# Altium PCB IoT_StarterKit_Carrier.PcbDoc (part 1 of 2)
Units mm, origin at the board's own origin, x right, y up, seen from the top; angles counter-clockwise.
Board outline 84.71 x 84.24 mm, 4 copper layers (Top, PWR, MID, Bottom), stack 1.612 mm thick; 101 components, 113 nets, 468 pads, 142 vias.
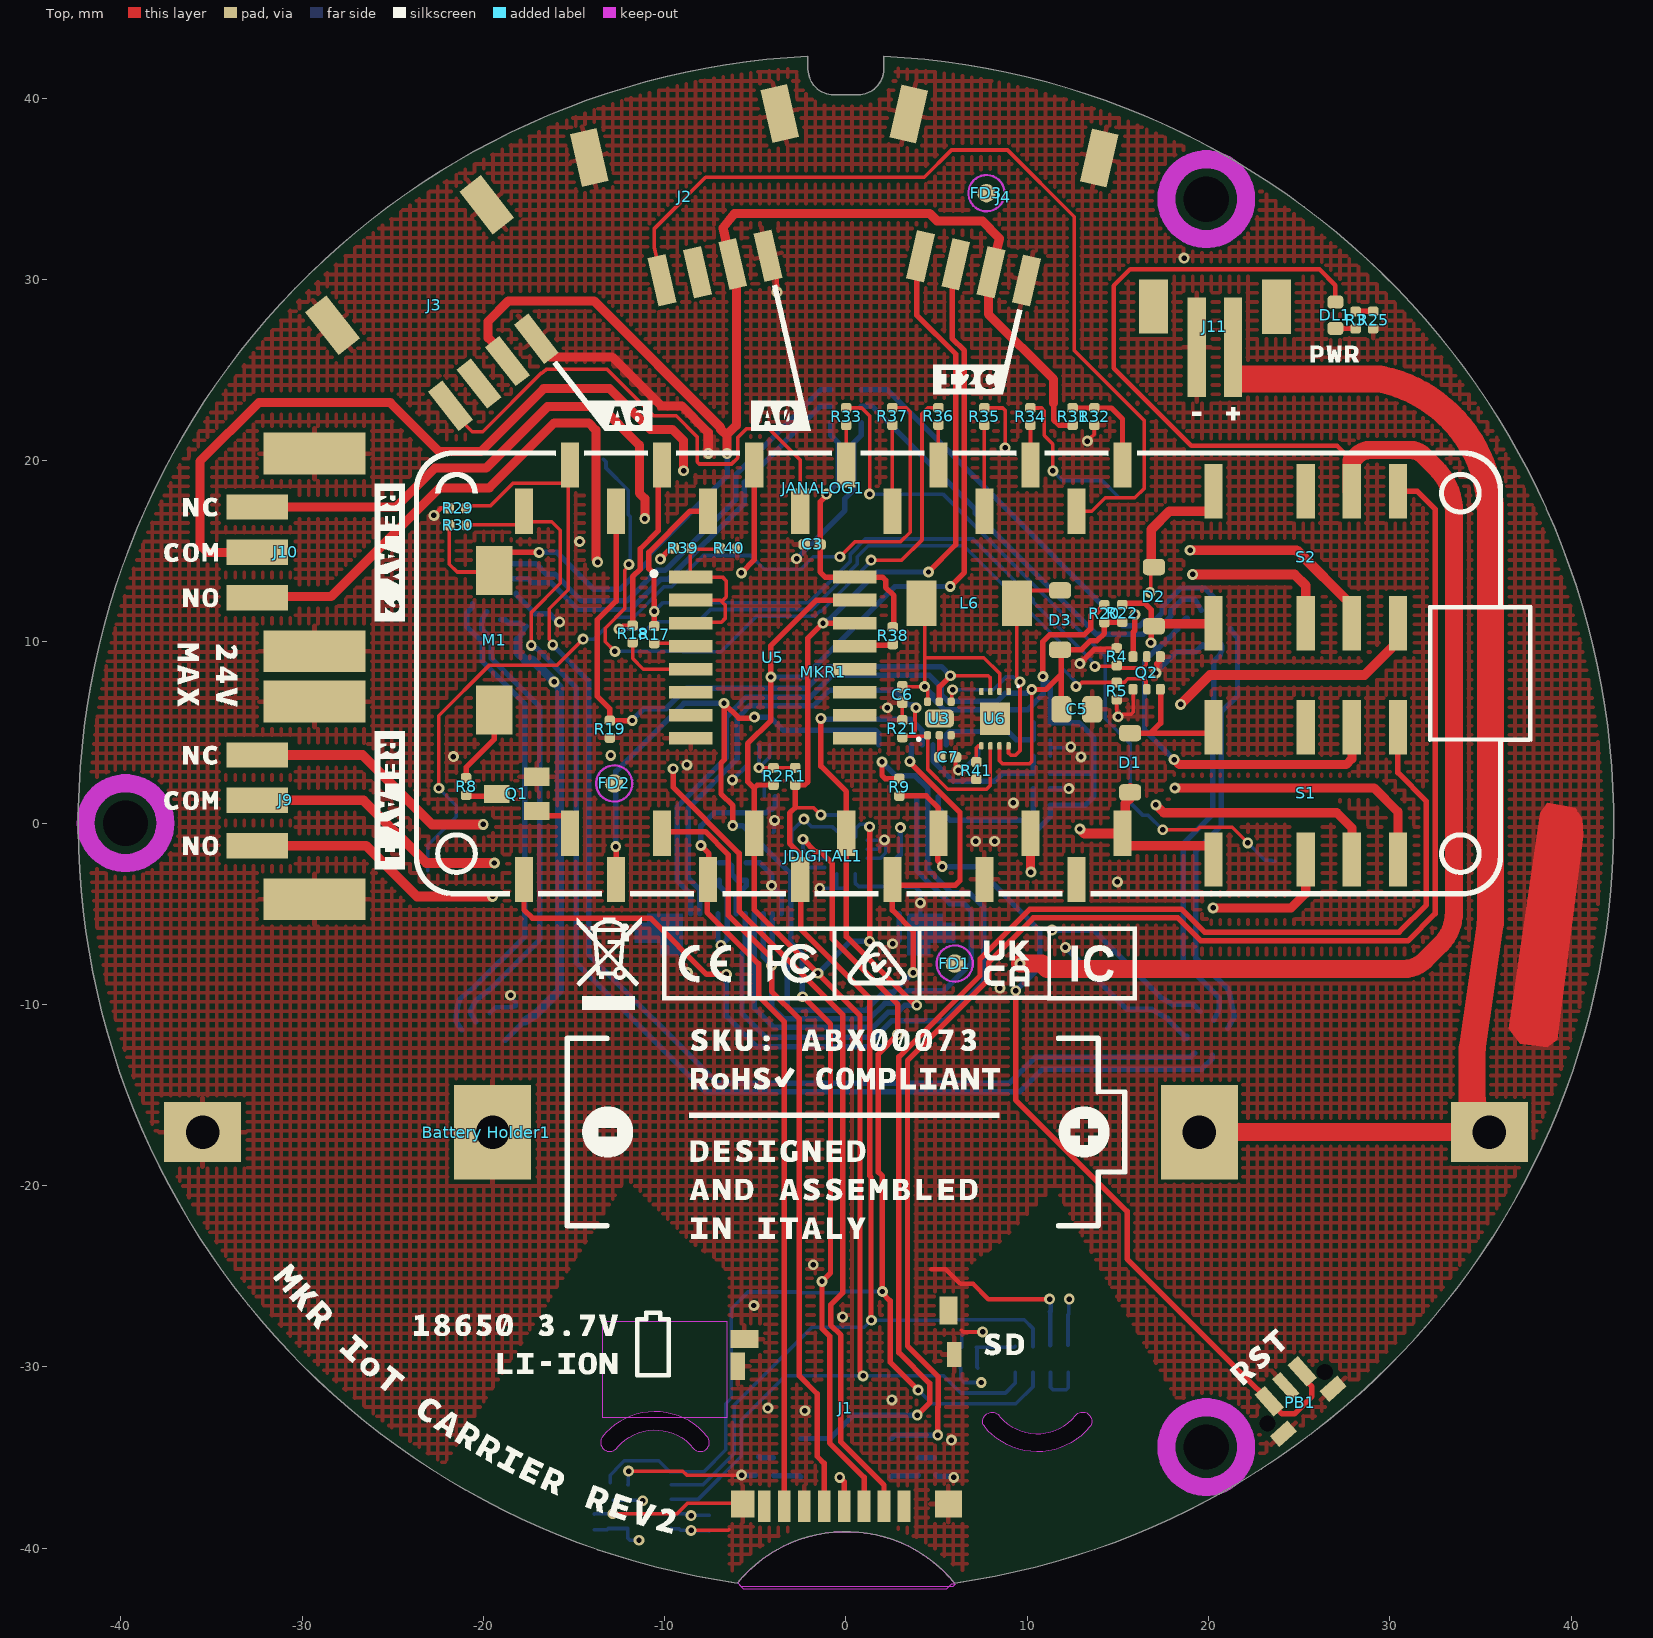
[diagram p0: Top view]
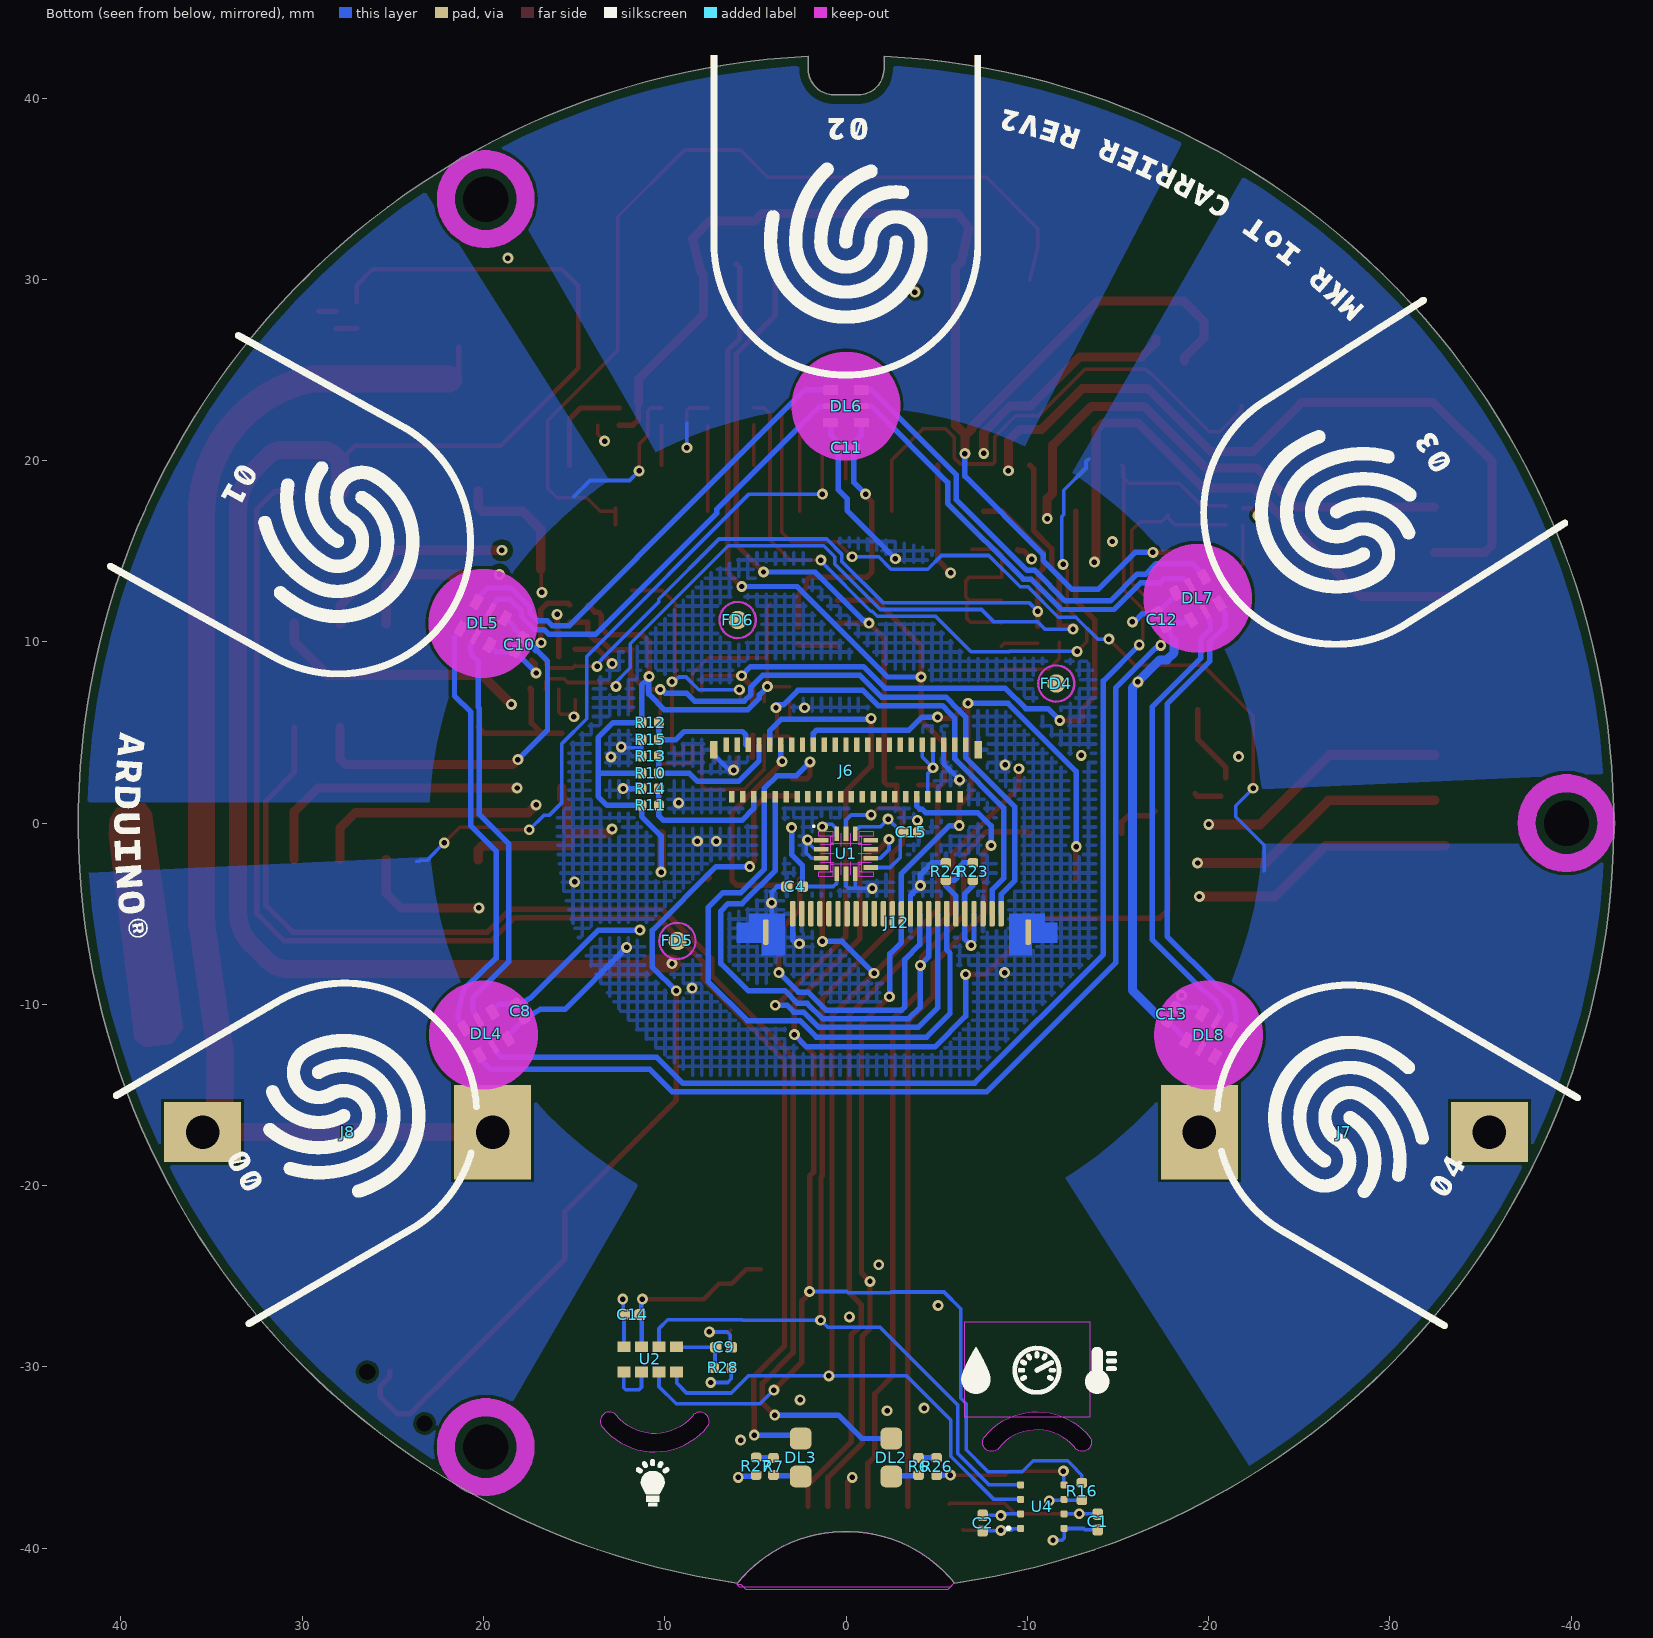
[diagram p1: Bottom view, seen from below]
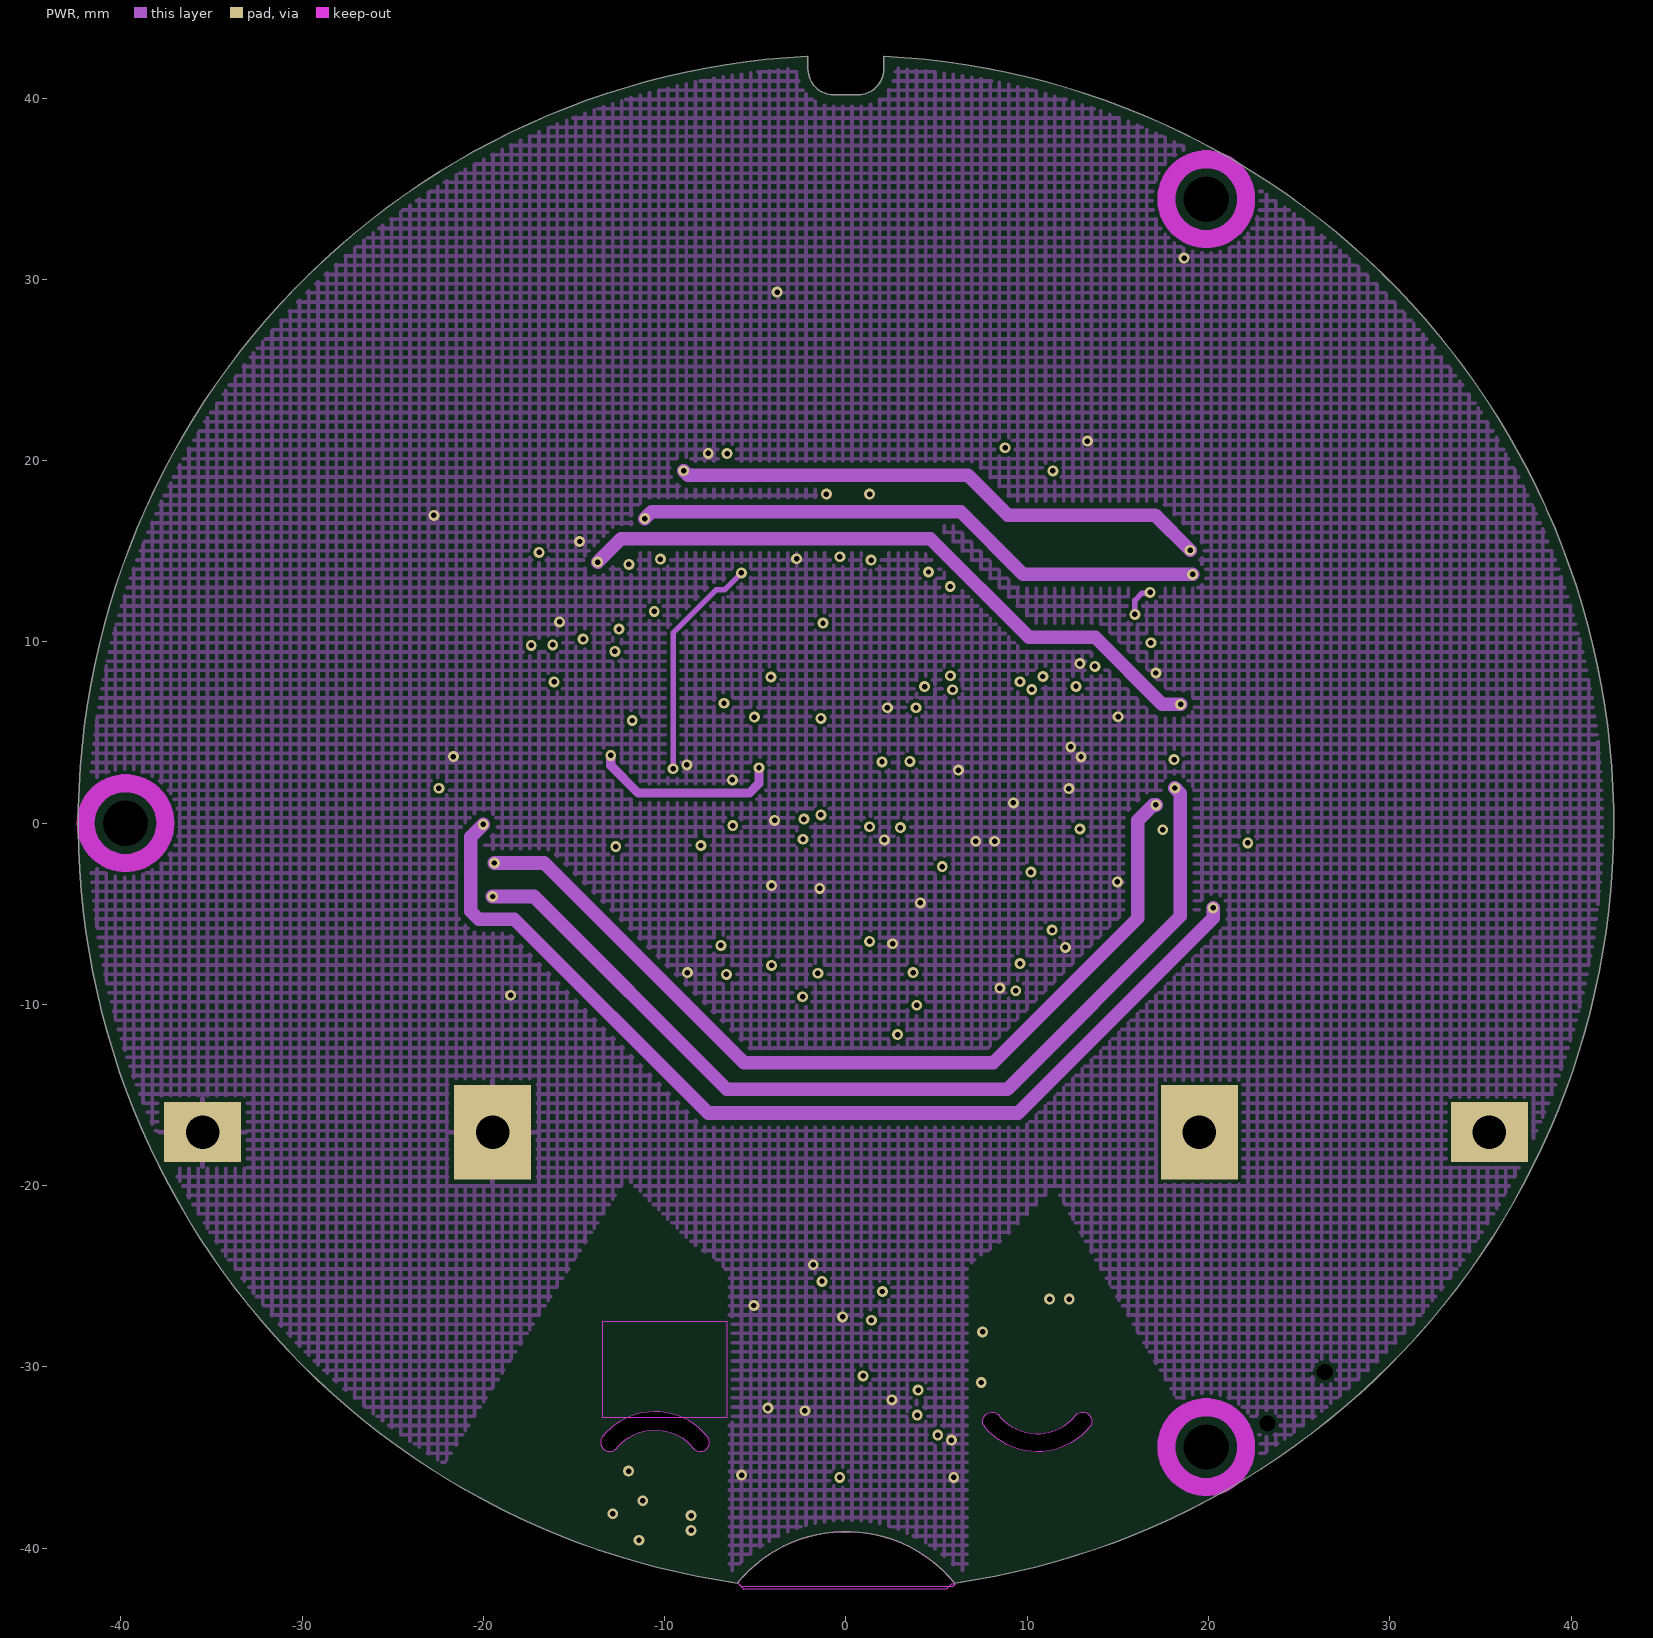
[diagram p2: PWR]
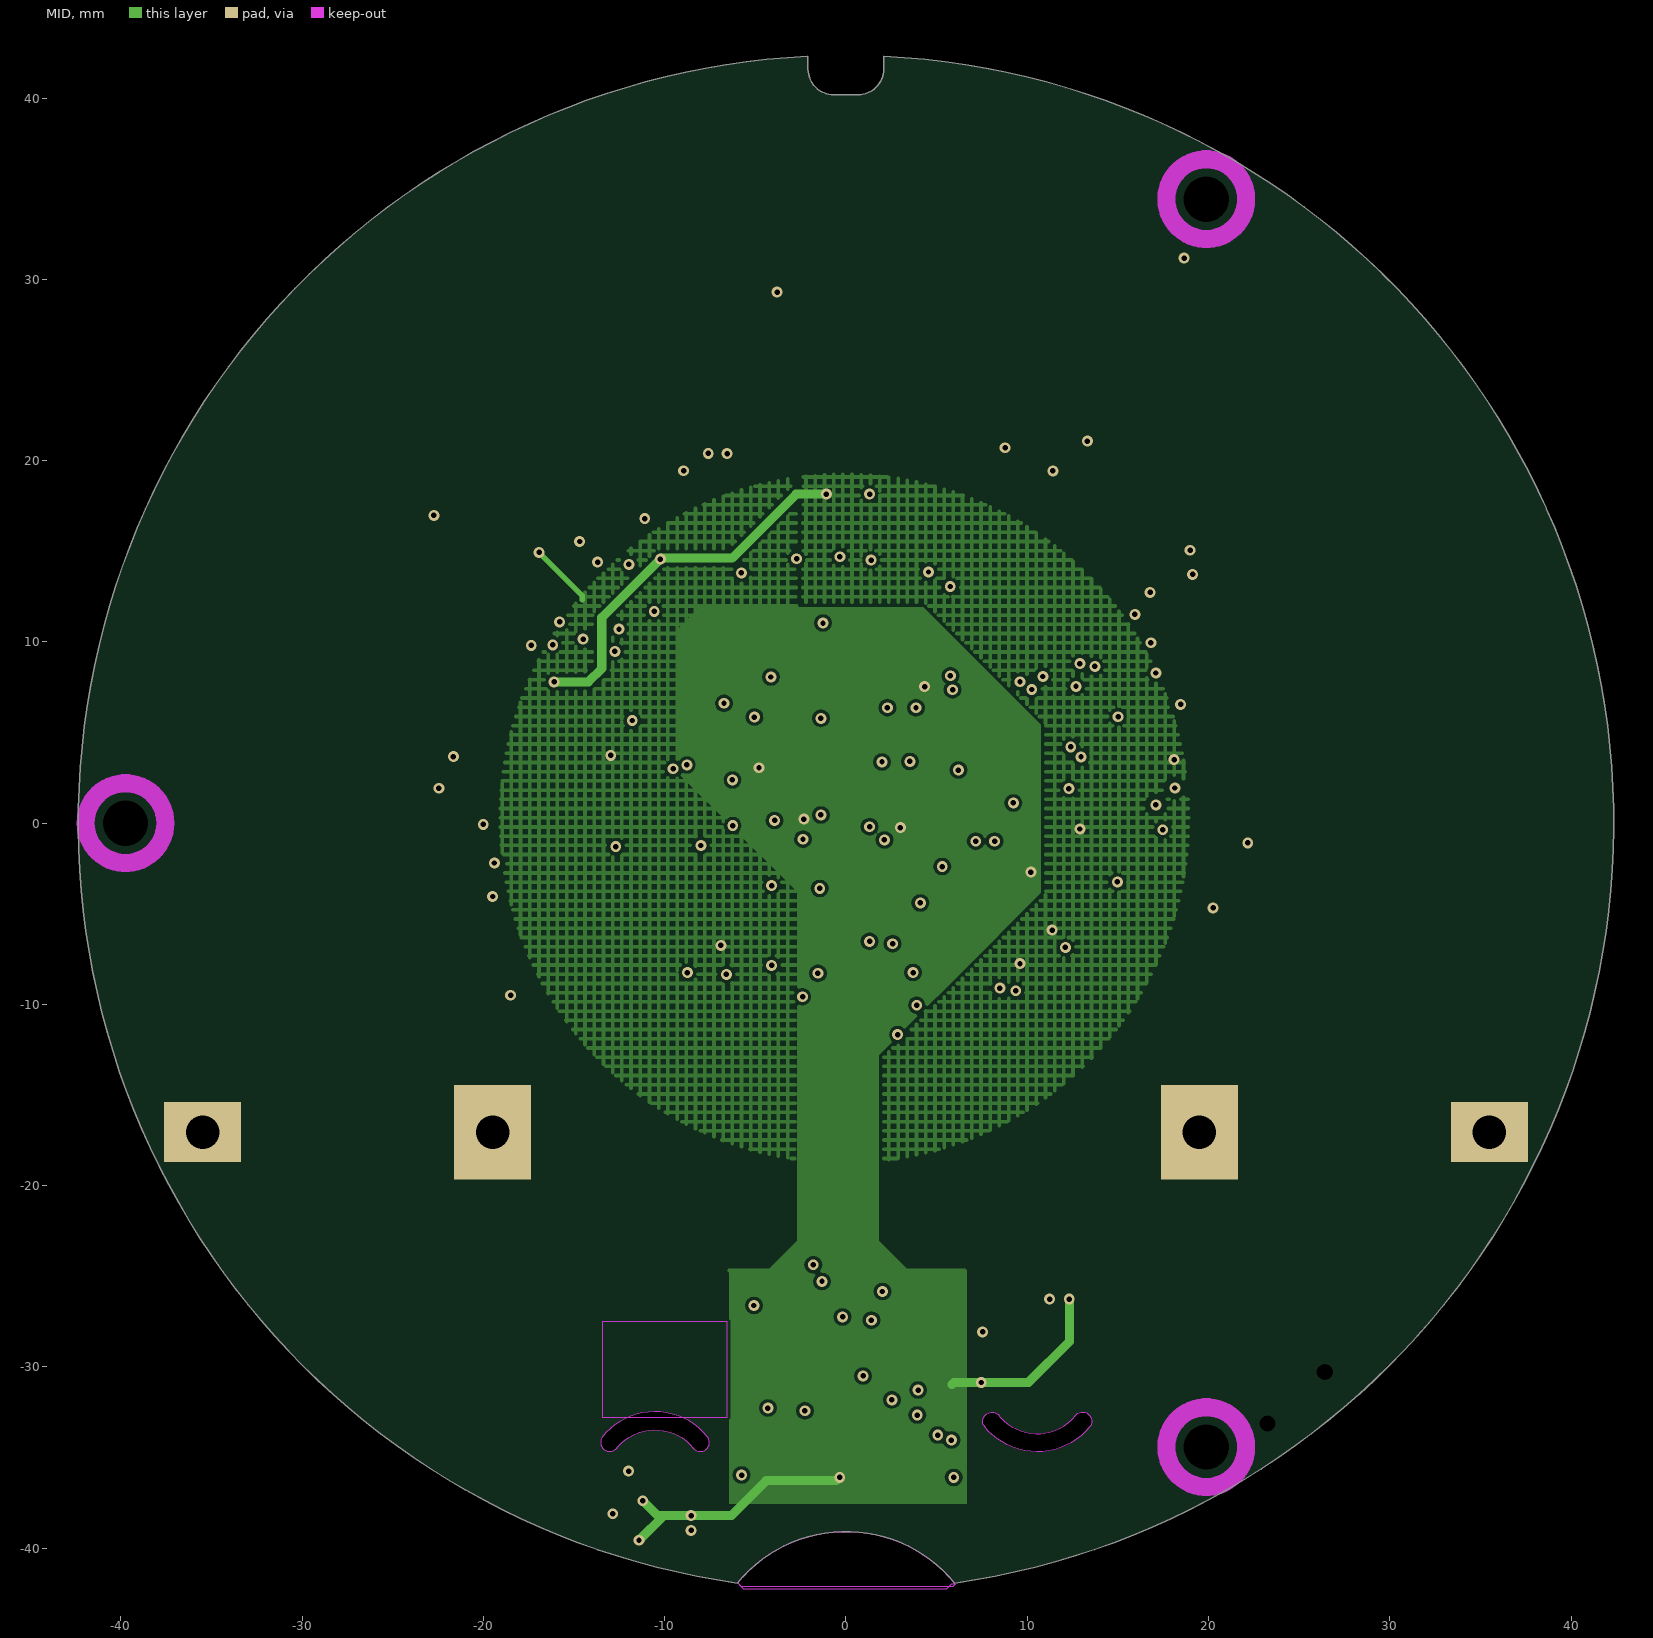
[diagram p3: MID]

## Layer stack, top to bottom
Top Solder: solder mask 0.01, Solder Resist, Dk 3.5
Top: signal copper 0.035
Dielectric 1: prepreg 0.356, FR-4, Dk 4.1
PWR: signal copper 0.035
Dielectric3: core 0.76, FR-4, Dk 4.8
MID: signal copper 0.035
Dielectric2: prepreg 0.356, FR-4, Dk 4.1
Bottom: signal copper 0.035
Bottom Solder: solder mask 0.0102, Solder Resist, Dk 3.5

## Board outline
-1.339,40.336 -1.079,40.228 -0.813,40.175 -0.672,40.168 0.656,40.168 0.797,40.175 1.063,40.228 1.323,40.336 1.558,40.493 1.757,40.692 1.914,40.927 2.022,41.187 2.074,41.453 2.081,41.594 2.081,42.306 2.082,42.306 cw(c0,0) 5.992,-41.931 ccw(c0,-46.8) -5.992,-41.931 cw(c0,0) -2.099,42.305 -2.098,42.285 -2.098,41.594 -2.091,41.453 -2.038,41.187 -1.93,40.927 -1.773,40.692 -1.574,40.493
cut-out: 7.614,-33.261 cw(c8.054,-33.008) 8.494,-32.755 ccw(c10.549,-30.949) 12.667,-32.68 cw(c13.055,-32.997) 13.555,-33.012 cw(c13.055,-32.997) 13.442,-33.314 cw(c10.549,-30.949)
cut-out: -13.475,-33.9 ccw(c-13.035,-34.153) -12.596,-34.406 cw(c-10.54,-36.212) -8.422,-34.481 ccw(c-8.035,-34.164) -7.534,-34.149 ccw(c-8.034,-34.164) -7.647,-33.847 ccw(c-10.54,-36.212)
cut-out: -5.63,-42.274 -5.983,-41.921 cw(c0,-46.8) 6.037,-41.989 5.805,-41.989 5.519,-42.274
cut-out: -5.783,-42.12 -5.983,-41.921 cw(c0,-46.8) 6.037,-41.989 5.896,-42.13

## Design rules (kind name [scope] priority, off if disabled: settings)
BoardOutlineClearance Silk [(OnLayer('top overlay') OR OnLayer('bottom overlay'))] p1: gap=0 ignorepadtopadclearanceinfootprint=FALSE
BoardOutlineClearance MouseBites [(ObjectKind = 'Pad') And (Name = 'Free-MOUSEBITES')] p2: gap=0 ignorepadtopadclearanceinfootprint=FALSE
BoardOutlineClearance BoardOutlineClearance_1 [IsPolygon] p3: gap=0.5 ignorepadtopadclearanceinfootprint=FALSE
BoardOutlineClearance general [All] p4: gap=0.3 ignorepadtopadclearanceinfootprint=FALSE
Clearance Clearance_Relay [InNetClass('Relay')] p1: gap=0.3 ignorepadtopadclearanceinfootprint=TRUE
Clearance [All] p2: gap=0.178 ignorepadtopadclearanceinfootprint=TRUE
HoleSize [All] p1: absolutevalues=TRUE maxlimit=2540 minlimit=0.3 maxpercent=80.000 minpercent=20.000
HoleToHoleClearance mdDrill [All] p1: gap=0.254 allowstackedmicrovias=TRUE
MinimumSolderMaskSliver [All] p1 off: minsoldermaskwidth=0.1
PasteMaskExpansion Expansion_SMDPaste_OFF [InPadClass('SMDPaste_OFF')] p1: expansion=0
PasteMaskExpansion mlMinCreamFrame [All] p2: expansion=0
PolygonConnect PolygonConnect_For_PolygonThermal_ON_Width120000_Gap100000 [InPolygonClass('PolygonThermal_ON_Width120000_Gap100000')] p1: connectstyle=Relief reliefconductorwidth=0.305 reliefentries=4 polygonreliefangle="90 Angle" airgapwidth=0.254
PolygonConnect PolygonConnect_For_PolygonThermal_OFF [InPolygonClass('PolygonThermal_OFF')] p2: connectstyle=Direct reliefconductorwidth=0.254 reliefentries=4 polygonreliefangle="90 Angle" airgapwidth=0.254
PolygonConnect PolygonConnect_For_PolygonThermal_ON_Width160000_Gap100000 [InPolygonClass('PolygonThermal_ON_Width160000_Gap100000')] p3: connectstyle=Relief reliefconductorwidth=0.406 reliefentries=4 polygonreliefangle="90 Angle" airgapwidth=0.254
PolygonConnect ThermalVias [IsVia] p4: connectstyle=Direct reliefconductorwidth=0.254 reliefentries=4 polygonreliefangle="90 Angle" airgapwidth=0.254
PolygonConnect [All] p5: connectstyle=Relief reliefconductorwidth=0.254 reliefentries=4 polygonreliefangle="90 Angle" airgapwidth=0.254
RoomDefinition SD-Card [InComponentClass('SD-Card')] p1 off: confinementstyle=ConfineIn formatcopy=TRUE lockcomponents=FALSE outline -290.242,-353.781 -239.442,-353.781 -239.442,-328.381 -290.242,-328.381
RoomDefinition "SC_capacitive buttons_6" [InComponentClass('SC_capacitive buttons_6')] p2 off: confinementstyle=ConfineIn formatcopy=TRUE lockcomponents=FALSE outline -290.242,-353.781 -239.442,-353.781 -239.442,-328.381 -290.242,-328.381
RoomDefinition Relays [InComponentClass('Relays')] p3 off: confinementstyle=ConfineIn formatcopy=TRUE lockcomponents=FALSE outline -290.242,-353.781 -239.442,-353.781 -239.442,-328.381 -290.242,-328.381
RoomDefinition OLED [InComponentClass('OLED')] p4 off: confinementstyle=ConfineIn formatcopy=TRUE lockcomponents=FALSE outline 43.957,-34.181 69.057,-34.181 69.057,-29.981 43.957,-29.981
RoomDefinition APDS-9306-065 [InComponentClass('APDS-9306-065')] p5 off: confinementstyle=ConfineIn formatcopy=TRUE lockcomponents=FALSE outline 43.957,-41.381 48.357,-41.381 48.357,-35.581 43.957,-35.581
RoomDefinition ABT-461-RC [InComponentClass('ABT-461-RC')] p6 off: confinementstyle=ConfineIn formatcopy=TRUE lockcomponents=FALSE outline -290.242,-353.781 -239.442,-353.781 -239.442,-328.381 -290.242,-328.381
RoomDefinition "IMU sensor" [InComponentClass('IMU sensor')] p7 off: confinementstyle=ConfineIn formatcopy=TRUE lockcomponents=FALSE outline -147.842,-244.081 -144.042,-244.081 -144.042,-239.481 -147.842,-239.481
RoomDefinition Controller [InComponentClass('Controller')] p8 off: confinementstyle=ConfineIn formatcopy=TRUE lockcomponents=FALSE outline -290.242,-353.781 -239.442,-353.781 -239.442,-328.381 -290.242,-328.381
RoomDefinition "Barometric Sensor" [InComponentClass('Barometric Sensor')] p9 off: confinementstyle=ConfineIn formatcopy=TRUE lockcomponents=FALSE outline -231.142,-346.481 -225.142,-346.481 -225.142,-342.481 -231.142,-342.481
RoomDefinition TOP [InComponentClass('TOP')] p10 off: confinementstyle=ConfineIn formatcopy=TRUE lockcomponents=FALSE outline -278.142,-341.681 -252.442,-341.681 -252.442,-273.381 -278.142,-273.381
RoutingVias [All] p1: holewidth=0.3 width=0.6 viastyle="Through Hole" minholewidth=0.3 minwidth=0.6 maxholewidth=0.3 maxwidth=0.6
SilkToSilkClearance [All] p1 off: silktosilkclearance=0.254
SilkToSolderMaskClearance [IsPad] p1 off: minsilkscreentomaskgap=0.1 clearancetoexposedcopper=TRUE
SolderMaskExpansion [IsVia] p1: expansion=0.102 istentingtop=TRUE
SolderMaskExpansion Expansion_SMDSolder_OFF [InPadClass('SMDSolder_OFF')] p2: expansion=0 istentingtop=FALSE
SolderMaskExpansion mlMinStopFrame [All] p3: expansion=0.1 istentingtop=FALSE
UnRoutedNet [All] p1: checkbadconnections=TRUE
Width [All] p1 off: maxlimit=254 minlimit=0.2 preferedwidth=0.3
23 further rules are at their usual default settings.

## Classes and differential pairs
net class Relay: NetS1_10 NetS2_10 S1_3_3 S1_4_3 S1_5_3 S2_3_3 S2_4_3 S2_5_3
component class SD-Card: J1
component class OLED: C5 C6 C7 D3 J6 J12 L6 R10 R11 R12 R13 R14 R15 R19 R20 R21 R22 R23 R24 R41 U3 U6
component class APDS-9306-065: C9 C14 R28 U2
component class ABT-461-RC: M1 Q1 R8
component class TOP: "Battery Holder1" C3 DL1 FD1 FD2 FD3 FD4 FD5 FD6 J2 J3 J4 J7 J8 J11 R3 R9 R16 R17 R18 R25 R29 R30 R31 R32 R38 R39 R40 U5
component class "IMU sensor": C4 C15 U1
component class Relays: D1 D2 DL2 DL3 J9 J10 Q2 R4 R5 R6 R7 R26 R27 S1 S2
component class "Barometric Sensor": C1 C2 U4
component class "SC_capacitive buttons_6": C8 C10 C11 C12 C13 DL4 DL5 DL6 DL7 DL8 R33 R34 R35 R36 R37
component class Controller: JANALOG1 JDIGITAL1 MKR1 PB1 R1 R2

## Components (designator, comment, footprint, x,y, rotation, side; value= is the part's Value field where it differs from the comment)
"Battery Holder1" "Battery Holder" "Battery Holder-Footprint-1" -19.834,-17.049 r0 top
C1 "GRM155R61H104KE19D" CAP-0402 -13.886,-38.554 r270 bottom value=100nF
C2 "GRM155R61H104KE19D" CAP-0402 -7.538,-38.621 r90 bottom value=100nF
C3 "GRM155R61H104KE19D" CAP-0402 -1.865,15.37 r0 top value=100nF
C4 "GRM155R61H104KE19D" CAP-0402 2.835,-3.5 r180 bottom value=100nF
C5 "GCM21BC72A105KE36L" CAP-0805 12.734,6.275 r180 top value=1µF
C6 "C0402C105K8PACTU" CAP-0402 3.107,7.091 r90 top value=1µF
C7 "C0402C224K9PACTU" CAP-0402 5.608,3.631 r180 top value=220nF
C8 "GRM155R61H104KE19D" CAP-0402 17.98,-10.38 r60 bottom value=100nF
C9 "C0402C105K8PACTU" CAP-0402 6.75,-28.924 r0 bottom value=1µF
C10 "GRM155R61H104KE19D" CAP-0402 18.034,9.844 r120 bottom value=100nF
C11 "GRM155R61H104KE19D" CAP-0402 -0.003,20.694 r180 bottom value=100nF
C12 "GRM155R61H104KE19D" CAP-0402 -17.419,11.228 r240 bottom value=100nF
C13 "GRM155R61H104KE19D" CAP-0402 -17.936,-10.548 r300 bottom value=100nF
C14 "C0402C105K8PACTU" CAP-0402 11.804,-27.11 r180 bottom value=1µF
C15 "GRM155R61H104KE19D" CAP-0402 -3.576,-0.516 r0 bottom value=100nF
D1 "PMEG6020AELRX" SOD123-1 15.674,3.33 r90 top
D2 "PMEG6020AELRX" SOD123-1 16.989,12.492 r90 top
D3 "1N4148W" SOD123-1 11.808,11.199 r90 top
DL1 "HSMG-C190" LEDC1608X80N-AK 27,28.018 r90 top
DL2 "KPT-2012YC" CHIPLED_0805 -2.5,-35 r270 bottom
DL3 "KPT-2012YC" CHIPLED_0805 2.5,-35 r270 bottom
DL4 "APA1022020-2018" APA102-2020-Footprint-1 19.856,-11.611 r60 bottom
DL5 "APA1022020-2018" APA102-2020-Footprint-1 20.028,11.015 r120 bottom
DL6 "APA1022020-2018" APA102-2020-Footprint-1 0,23 r180 bottom
DL7 "APA1022020-2018" APA102-2020-Footprint-1 -19.4,12.4 r240 bottom
DL8 "APA1022020-2018" APA102-2020-Footprint-1 -20,-11.691 r300 bottom
FD1 "Fiducial mark 1.5mm" FIDUCIAL-1.5 6,-7.75 r0 top
FD2 "Fiducial mark 1.5mm" FIDUCIAL-1.5 -12.786,2.186 r0 top
FD3 "Fiducial mark 1.5mm" FIDUCIAL-1.5 7.75,34.75 r0 top
FD4 "Fiducial mark 1.5mm" FIDUCIAL-1.5 -11.6,7.7 r180 bottom
FD5 "Fiducial mark 1.5mm" FIDUCIAL-1.5 9.3,-6.5 r180 bottom
FD6 "Fiducial mark 1.5mm" FIDUCIAL-1.5 5.975,11.202 r180 bottom
J1 "114-00841-68" AMPHENOL_114-00841-68 -0.002,-31.806 r0 top locked (schematic designator J?)
J2 "320110032" 320110032-Footprint-1 -7.243,30.718 r13 top locked
J3 "320110032" 320110032-Footprint-1 -19.519,24.95 r38 top locked
J4 "320110032" 320110032-Footprint-1 7.051,30.704 r347 top locked
J6 "FH26W-45S-0.3SHW(60)" FH26W-45S-0.3SHW(60)-Footprint-1 0,3 r0 bottom locked
J7 "254TR" 254TR-Footprint-1 -35.5,-17.049 r0 top
J8 "254TR" 254TR-Footprint-1 35.5,-17.049 r180 top
J9 "1771101" 1771101-Footprint-1 -31.899,1.255 r270 top locked
J10 "1771101" 1771101-Footprint-1 -31.899,14.935 r270 top locked
J11 "B2B-PH-SM4-TB(LF)(SN)" "New footprint 1" 20.353,31 r0 top locked
J12 "SFV24R-1STBE1HLF" SFV24R-1STBE1HLF-Footprint-1 -2.81,-5 r180 bottom locked
JANALOG1 "21TW-547" 21TW-332-Footprint-1 15.256,19.751 r180 top
JDIGITAL1 "21TW-546" 21TW-331-Footprint-1 -17.764,-0.569 r180 top
L6 "SRR0604-100ML" SRR0604-100ML-Footprint-1 6.8,12.121 r0 top
M1 "ABT-461-RC" ABT-461-RC-Footprint-1 -19.404,10.096 r270 top
MKR1 "MKRBOARD-SMD-ALTERNATE" MKRSHIELD 37.452,20.819 r180 top locked
PB1 "TL3340AF160QG" TL3340AF160QG-Footprint-1 24.88,-31.76 r42 top
Q1 "2N7002KT1G" SOT23 -18.161,1.609 r90 top
Q2 "BSS138PS" SOT363 16.589,8.281 r180 top
R1 "CRCW040210K0FKED" RES-0402 -2.8,2.576 r90 top value=10k
R2 "CRCW040210K0FKED" RES-0402 -4,2.576 r90 top value=10k
R3 "CRCW0402330RJNED" RES-0402 28.118,27.753 r270 top value=330
R4 "CRCW040210K0FKED" RES-0402 14.937,9.172 r90 top value=10k
R5 "CRCW040210K0FKED" RES-0402 14.937,7.284 r270 top value=10k
R6 "RC0402JR-07270RL" RES-0402 -4,-35.5 r270 bottom value=270
R7 "RC0402JR-07270RL" RES-0402 4,-35.5 r270 bottom value=270
R8 "CRCW04020000Z0EDC" RES-0402 -20.959,2.015 r90 top value=0
R9 "CRCW04020000Z0EDC" RES-0402 2.95,1.975 r270 top value=0
R10 "CRCW040210K0FKED" RES-0402 10.8,2.749 r0 bottom value=10k
R11 "CRCW040210K0FKED" RES-0402 10.8,0.973 r0 bottom value=10k
R12 "CRCW040210K0FKED" RES-0402 10.8,5.547 r0 bottom value=10k
R13 "CRCW04020000Z0EDC" RES-0402 10.8,3.695 r180 bottom value=0
R14 "CRCW04020000Z0EDC" RES-0402 10.8,1.9 r180 bottom value=0
R15 "CRCW04020000Z0EDC" RES-0402 10.8,4.6 r180 bottom value=0
R16 "CRCW040210K0FKED" RES-0402 -13.013,-36.875 r270 bottom value=10k
R17 "CRCW04020000Z0EDC" RES-0402 -10.579,10.391 r90 top value=0
R18 "CRCW04020000Z0EDC" RES-0402 -11.77,10.437 r90 top value=0
R19 "CRCW040210K0FKED" RES-0402 -13.027,5.18 r90 top value=10k
R20 "CRCW04020000Z0EDC" RES-0402 14.259,11.553 r90 top value=0
R21 "RC0402FR-0710RL" RES-0402 3.116,5.207 r270 top value=10
R22 "CRCW04020000Z0EDC" RES-0402 15.241,11.566 r270 top value=0
R23 "CRCW040210K0FKED" RES-0402 -7,-2.674 r270 bottom value=10k
R24 "CRCW04020000Z0EDC" RES-0402 -5.515,-2.674 r270 bottom value=0
R25 "CRCW04020000Z0EDC" RES-0402 29.084,27.748 r90 top value=0
R26 "CRCW04020000Z0EDC" RES-0402 -5,-35.5 r90 bottom value=0
R27 "CRCW04020000Z0EDC" RES-0402 4.958,-35.483 r90 bottom value=0
R28 "RC0402FR-0722RL" RES-0402 6.794,-30.059 r180 bottom value=22
R29 "RC0402FR-074K7L" RES-0402 -21.43,17.359 r0 top value=4.7k
R30 "RC0402FR-074K7L" RES-0402 -21.408,16.437 r0 top value=4.7k
R31 "CRCW04021K00FKEDC" RES-0402 12.5,22.426 r270 top value=1k
R32 "CRCW04021K00FKEDC" RES-0402 13.7,22.426 r90 top value=1k
R33 "CRCW04020000Z0EDC" RES-0402 0.016,22.426 r90 top value=0
R34 "CRCW04020000Z0EDC" RES-0402 10.176,22.426 r90 top value=0
R35 "CRCW04020000Z0EDC" RES-0402 7.636,22.426 r90 top value=0
R36 "CRCW04020000Z0EDC" RES-0402 5.096,22.436 r90 top value=0
R37 "CRCW04020000Z0EDC" RES-0402 2.556,22.436 r90 top value=0
R38 "CRCW040210K0FKED" RES-0402 2.58,10.334 r90 top value=10k
R39 "CRCW04020000Z0EDC" RES-0402 -9.001,15.168 r180 top value=0
R40 "CRCW04020000Z0EDC" RES-0402 -6.477,15.153 r180 top value=0
R41 "RC0402FR-0710RL" RES-0402 7.19,2.895 r90 top value=10
S1 "V23079G2001B301" EE2-5NU-L-Footprint-1 26.234,1.64 r90 top locked
S2 "V23079G2001B301" EE2-5NU-L-Footprint-1 26.234,14.665 r90 top locked
U1 "LSM6DSOXTR" VFLGA14 0,-1.7 r180 bottom
U2 "APDS-9660" APDS-9660-Footprint-1 10.8,-29.588 r0 bottom
U3 "LV52204MTTBG" QFN65P200X200X80_HS-7L 5.15,5.768 r0 top
U4 "BME688" BME680-Footprint-1 -10.83,-37.713 r0 bottom
U5 "PCF8574T/3,512" SOIC127P1030X265-16N -4.05,9.128 r0 top
U6 "ISL97634IRT26Z-TK" PQFN0P300X200X80_HS-9L 8.218,5.761 r270 top

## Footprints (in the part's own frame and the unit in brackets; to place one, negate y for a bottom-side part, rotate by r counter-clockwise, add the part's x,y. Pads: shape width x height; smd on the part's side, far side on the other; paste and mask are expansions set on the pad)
21TW-331-Footprint-1 [mm]
  rect 1x2.5 smd: 1(0,2.54) 2(-2.54,0) 3(-5.08,2.54) 4(-7.62,0) 5(-10.16,2.54) 6(-12.7,0) 7(-15.24,2.54) 8(-17.78,0) 9(-20.32,2.54) 10(-22.86,0) 11(-25.4,2.54) 12(-27.94,0) 13(-30.48,2.54) 14(-33.02,0)
  body extent -34.29,-1.02 1.27,3.56, height 9.39
21TW-332-Footprint-1 [mm]
  rect 1x2.5 smd: 1(0,0) 2(2.54,2.54) 3(5.08,0) 4(7.62,2.54) 5(10.16,0) 6(12.7,2.54) 7(15.24,0) 8(17.78,2.54) 9(20.32,0) 10(22.86,2.54) 11(25.4,0) 12(27.94,2.54) 13(30.48,0) 14(33.02,2.54)
  body extent -1.27,-1.02 34.29,3.56, height 9.39
254TR-Footprint-1 [mm]
  rect 4.24x3.3 hole 1.85: 1(0,0)
  rect 4.24x3.3 smd far side: 1(0,0)
  rect 4.24x5.2 hole 1.85: 2(16,0)
  rect 4.24x5.2 smd far side paste+0: 2(16,0)
  body extent 0.6,-9.3 14.4,9.3, height 19.8
1771101-Footprint-1 [mm]
  rect 1.4x3.4 smd: 1(-2.5,-0.573) 2(0,-0.573) 3(2.5,-0.573)
  rect 2.3x5.6 smd: MP1(-5.45,2.577) MP2(5.45,2.577)
  body extent -6.3,-1.92 6.3,5.08, height 9
320110032-Footprint-1 [mm] "Default PCB Component"
  rect 1.01x2.74 smd: 1(-3,-0.1) 2(-1,-0.1) 3(1,-0.1) 4(3,-0.1)
  rect 1.5x3 smd: SS1(-5.4,7.4) SS2(5.4,7.4)
  body extent -6,-1.14 6,8.81, height 5.01
ABT-461-RC-Footprint-1 [mm]
  rect 2.7x2 smd: 1(-3.85,0) 2(3.85,0)
  body extent -5.25,-4.63 5.25,5.87, height 2.67
AMPHENOL_114-00841-68 [mm]
  rect 0.7x1.75 smd: 1(3.2,-5.888) 2(2.1,-5.888) 3(1,-5.888) 4(-0.1,-5.888) 5(-1.2,-5.888) 6(-2.3,-5.888) 7(-3.4,-5.888) 8(-4.5,-5.888)
  rect 1x1.55 smd: CD1(5.65,4.912)
  rect 1.55x1 smd: CD2(-5.602,3.337)
  rect 1.3x1.5 smd: SH1(-5.7,-5.76)
  rect 1.5x1.5 smd: SH2(5.65,-5.76)
  rect 0.8x1.4 smd: SH3(5.975,2.487)
  rect 0.8x1.5 smd: SH4(-5.975,1.837)
  body extent -6,-10.29 6,4.99, height 1.6
APA102-2020-Footprint-1 [mil]
  rect 31.5x19.69 smd: 1(33.46,35.43) 3(33.46,-35.43) 4(-33.46,-35.43) 6(-33.46,35.43)
  rect 31.5x11.81 smd: 2(33.46,0) 5(-33.46,0)
  body extent -39,-39 44,39, height 36
APDS-9660-Footprint-1 [mm]
  rect 0.72x0.6 smd mask+0.05: 1(-1.455,0.7) 2(-0.485,0.7) 3(0.485,0.7) 4(1.455,0.7) 5(1.455,-0.7) 6(0.485,-0.7) 7(-0.485,-0.7) 8(-1.455,-0.7)
  body extent -1.97,-1.18 1.97,1.18, height 1.3
"Battery Holder-Footprint-1" [mm]
BME680-Footprint-1 [mm]
  rrect50% 0.4x0.4 smd: 1(1.2,1.2) 2(1.2,0.4) 3(1.2,-0.4) 4(1.2,-1.2) 5(-1.2,-1.2) 6(-1.2,-0.4) 7(-1.2,0.4) 8(-1.2,1.2)
  silkscreen extent 1.83,1.16 1.89,1.21
CAP-0402 [mm] "Chip Capacitor, 2-Leads, Body  0402 (in) 1005 (mm), IPC Medium Density"
  rrect52% 0.63x0.58 smd mask+0: 1(-0.435,0) 2(0.435,0)
  body extent -0.5,-0.25 0.5,0.25, height 0.5
CAP-0805 [mm] "Chip Capacitor, Body 0805 imperial, 2.0x1.2mm, IPC Medium Density"
  rrect45% 1.11x1.47 smd mask+0: 1(-0.85,0) 2(0.85,0)
  body extent -1,-0.62 1,0.63, height 1.25
CHIPLED_0805 [mm]
  rrect50% 1.2x1.2 smd: A(-1.05,0) C(1.05,0)
  body extent -1.04,-0.45 1.02,0.46, height 0.85
EE2-5NU-L-Footprint-1 [mm]
  rect 3x1 smd: 1(-3.65,5.95) 3(-3.65,0.87) 4(-3.65,-1.67) 5(-3.65,-4.21) 8(3.65,-4.21) 9(3.65,-1.67) 10(3.65,0.87) 12(3.65,5.95)
  body extent -4.7,-7.75 4.8,7.25, height 10.01
FH26W-45S-0.3SHW(60)-Footprint-1 [mm]
  rect 0.3x0.8 smd mask+0.05: 1(-6.6,-1.325) 3(-6,-1.325) 5(-5.4,-1.325) 7(-4.8,-1.325) 9(-4.2,-1.325) 11(-3.6,-1.325) 13(-3,-1.325) 15(-2.4,-1.325) 17(-1.8,-1.325) 19(-1.2,-1.325) 21(-0.6,-1.325) 23(0,-1.325) 25(0.6,-1.325) 27(1.2,-1.325) 29(1.8,-1.325) 31(2.4,-1.325) 33(3,-1.325) 35(3.6,-1.325) 37(4.2,-1.325) 39(4.8,-1.325) 41(5.4,-1.325) 43(6,-1.325) 45(6.6,-1.325)
  rect 0.3x0.65 smd mask+0.05: 2(-6.3,1.55) 4(-5.7,1.55) 6(-5.1,1.55) 8(-4.5,1.55) 10(-3.9,1.55) 12(-3.3,1.55) 14(-2.7,1.55) 16(-2.1,1.55) 18(-1.5,1.55) 20(-0.9,1.55) 22(-0.3,1.55) 24(0.3,1.55) 26(0.9,1.55) 28(1.5,1.55) 30(2.1,1.55) 32(2.7,1.55) 34(3.3,1.55) 36(3.9,1.55) 38(4.5,1.55) 40(5.1,1.55) 42(5.7,1.55) 44(6.3,1.55)
  rect 0.4x0.95 smd mask+0.05: MP1(-7.3,-1.05) MP2(7.3,-1.05)
  body extent -7.5,-1.78 7.5,1.73, height 1
FIDUCIAL-1.5 [mil]
  rrect100% 40x40 smd paste-100: 1(0,0)
  Top keep-out circle w5: c0,0 r39.37
LEDC1608X80N-AK [mm]
  rrect50% 0.72x0.87 smd: A(0.725,0) C(-0.725,0)
  body extent -0.8,-0.4 0.8,0.4, height 0.79
MKRSHIELD [mm]
  rect 1x2.5 smd: 0(42.516,1.068) 1(45.056,3.608) 2(47.596,1.068) 3(50.136,3.608) 4(52.676,1.068) 5(55.216,3.608) 5V(22.196,21.388) 6(55.216,23.928) 7(52.676,21.388) 8(50.136,23.928) 9(47.596,21.388) 10(45.056,23.928) 11(42.516,21.388) 12(39.976,23.928) 13(37.436,21.388) 14(34.896,23.928) A0(24.736,3.608) A1(27.276,1.068) A2(29.816,3.608) A3(32.356,1.068) A4(34.896,3.608) A5(37.436,1.068) A6(39.976,3.608) AREF(22.196,1.068) GND(29.816,23.928) RST(32.356,21.388) VCC(27.276,21.388) VIN(24.736,23.928)
"New footprint 1" [mm]
  rect 1x5.5 smd: 1(-1,-4.75) 2(1,-4.75)
  rect 1.6x3 smd: MP1(-3.4,-2.5) MP2(3.4,-2.51)
  body extent -3.97,-6.91 3.97,0.09, height 6.6
PQFN0P300X200X80_HS-9L [mm] "PQFN, 8-Leads, Body 3.00x2.00mm, Pitch 0.00mm/0.50mm, Thermal Pad 1.80x1.65mm, IPC High Density"
  rrect50% 0.4x0.25 smd: 1(-1.5,0.75) 2(-1.5,0.25) 3(-1.5,-0.25) 4(-1.5,-0.75) 5(1.5,-0.75) 6(1.5,-0.25) 7(1.5,0.25) 8(1.5,0.75)
  rect 1.8x1.65 smd paste-2: 9(0,0)
  silkscreen extent -1.82,1.23 -1.73,1.33, body extent -1.48,-0.98 1.47,0.98, height 0.8
QFN65P200X200X80_HS-7L [mm] "QFN, 6-Leads, Body 2.00x2.00mm, Pitch 0.65mm, Thermal Pad 1.7X1.1mm, IPC High Density"
  rrect50% 0.4x0.45 smd mask+0.05: 1(-0.65,-0.925) 2(0,-0.925) 3(0.65,-0.925) 4(0.65,0.925) 5(0,0.925) 6(-0.65,0.925)
  rrect50% 1.6x1 smd mask+0.05: 7(0,0)
  silkscreen extent -1.19,-1.19 -1.09,-1.09, body extent -1,-1 1,1, height 0.8
RES-0402 [mm] "Chip Resistor, 2-Leads, Body  0402 (in) 1005 (mm), IPC Medium Density"
  rrect51% 0.55x0.58 smd mask+0: 1(-0.475,0) 2(0.475,0)
  body extent -0.5,-0.25 0.5,0.25, height 0.34
SFV24R-1STBE1HLF-Footprint-1 [mm]
  rrect50% 0.3x1.4 smd: 1(-5.75,0) 2(-5.25,0) 3(-4.75,0) 4(-4.25,0) 5(-3.75,0) 6(-3.25,0) 7(-2.75,0) 8(-2.25,0) 9(-1.75,0) 10(-1.25,0) 11(-0.75,0) 12(-0.25,0) 13(0.25,0) 14(0.75,0) 15(1.25,0) 16(1.75,0) 17(2.25,0) 18(2.75,0) 19(3.25,0) 20(3.75,0) 21(4.25,0) 22(4.75,0) 23(5.25,0) 24(5.75,0)
  rrect50% 0.3x1.4 smd paste+0 mask+0: MP1(-7.239,-1.016) MP2(7.239,-1.016)
  Top region: 6.2,0 6.2,-2.3 7.45,-2.3 7.45,-1.6 8.85,-1.6 8.85,-0.5 8.15,-0.5 8.15,0
  Top region: -6.2,0 -6.2,-2.3 -7.45,-2.3 -7.45,-1.6 -8.85,-1.6 -8.85,-0.5 -8.15,-0.5 -8.15,0
  body extent -8.75,-4.39 8.75,0.51, height 1.8
SOD123-1 [mm]
  rrect50% 0.91x1.22 smd: A(1.635,0) C(-1.635,0)
  body extent -1.78,-0.78 1.92,0.82, height 1.27
SOIC127P1030X265-16N [mm] "SOIC, 16-Leads, Body 10,30x7,50mm, Pitch 1,27mm, IPC Medium Density"
  rect 2.4x0.7 smd: 1(-4.525,4.445) 2(-4.525,3.175) 3(-4.525,1.905) 4(-4.525,0.635) 5(-4.525,-0.635) 6(-4.525,-1.905) 7(-4.525,-3.175) 8(-4.525,-4.445) 9(4.525,-4.445) 10(4.525,-3.175) 11(4.525,-1.905) 12(4.525,-0.635) 13(4.525,0.635) 14(4.525,1.905) 15(4.525,3.175) 16(4.525,4.445)
  silkscreen extent -6.67,4.51 -6.42,4.76, body extent -5.16,-5.25 5.16,5.25, height 2.65
SOT23 [mm]
  rect 1x1.4 smd: 1(-0.95,-1.1) 2(0.95,-1.1) 3(0,1.1)
  body extent -1.5,-1.25 1.5,1.25, height 1.05
SOT363 [mm]
  rrect50% 0.5x0.6 smd mask+0.05: 1(-0.75,-0.9) 3(0.75,-0.9) 4(0.75,0.9) 6(-0.75,0.9)
  rrect50% 0.4x0.6 smd mask+0.05: 2(0,-0.9) 5(0,0.9)
  body extent -1.05,-1.15 1.05,1.15, height 1
SRR0604-100ML-Footprint-1 [mm]
  rect 1.65x2.5 smd: 1(-2.625,0) 2(2.625,0)
  body extent -3.25,-3.25 3.25,3.25, height 4.63
TL3340AF160QG-Footprint-1 [mm]
  rect 0.75x1.6 smd mask+0.05: 1(-1.225,0.925) 3(1.225,0.925)
  rect 0.6x1.6 smd mask+0.05: 2(0,0.925)
  rect 1.3x0.8 smd mask+0.05: MNT(-1.85,-0.925) MNT(1.85,-0.925)
  round 0.5 hole 0.9 unplated: NC1(-2.125,0.075) NC2(2.125,0.075)
  body extent -2.25,-1.98 2.25,1.69, height 3.3
VFLGA14 [mm]
  rect 0.8x0.25 smd mask+0.05: 1(-1.375,0.75) 2(-1.375,0.25) 3(-1.375,-0.25) 4(-1.375,-0.75) 8(1.375,-0.75) 9(1.375,-0.25) 10(1.375,0.25) 11(1.375,0.75)
  rect 0.25x0.8 smd mask+0.05: 5(-0.5,-1.1) 6(0,-1.1) 7(0.5,-1.1) 12(0.5,1.1) 13(0,1.1) 14(-0.5,1.1)
  Top keep-out region: -0.83,-0.98 -0.83,-0.58 -0.74,-0.58 -0.74,-0.98
  Top keep-out region: 0.74,-0.98 0.74,-0.58 0.83,-0.58 0.83,-0.98
  Top keep-out region: 0.74,0.58 0.74,0.98 0.83,0.98 0.83,0.58
  Top keep-out region: -0.83,0.58 -0.83,0.98 -0.74,0.98 -0.74,0.58
  Top keep-out region: -1.5,-1.25 -1.5,-0.98 -0.74,-0.98 -0.74,-1.25
  Top keep-out region: 0.74,-1.25 0.74,-0.98 1.5,-0.98 1.5,-1.25
  Top keep-out region: 0.74,0.98 0.74,1.25 1.5,1.25 1.5,0.98
  Top keep-out region: -1.5,0.98 -1.5,1.25 -0.74,1.25 -0.74,0.98
  Top keep-out region: -0.83,-0.58 -0.83,0.58 0.83,0.58 0.83,-0.58
  Top keep-out lines w0.01: 1.4,-0.5 0.67,-0.5 ; 1.4,0 0.67,0 ; 1.4,0.5 0.67,0.5 ; 0.25,-1.15 0.25,-0.42 ; 0.25,0.42 0.25,1.15 ; -0.25,-1.15 -0.25,-0.42 ; -0.25,0.42 -0.25,1.15 ; -0.67,-0.5 -1.4,-0.5 ; -0.67,0 -1.4,0 ; -0.67,0.5 -1.4,0.5
  silkscreen extent -1.83,1.47 -1.73,1.57, body extent -1.55,-1.3 1.55,1.3, height 0.86

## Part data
"Battery Holder1": library part UT0019-A.1, "Battery holder marker"
C1 C2 C3 C4 C8 C10 C11 C12 C13 C15: library part C0015-A.11, "CAP CHIP 0402 100nF 50V X5R 10%", Case Code (Imperial)=0402, Case Code (Metric)=1005, Dielectric=X5R, Manufacturer=Murata, Tolerance=10%, Voltage=50V
C5: library part C0084-A.9, "CAP CHIP 0805 1uF 100V X7S 10%", Case Code (Imperial)=0805, Case Code (Metric)=2012, Dielectric=X7S, Manufacturer=Murata, Tolerance=10%, Voltage=100V
C6 C9 C14: library part C0017-A.11, "CAP CHIP 0402 1uF 10V X5R 10%", Case Code (Imperial)=0402, Case Code (Metric)=1005, Dielectric=X5R, Manufacturer=KEMET, Manufacturer 2=AVX, Manufacturer Part Number 2=GRM155R61A105KE15D, Tolerance=10%, Voltage=10V
C7: library part C0088-A.10, "CAP CHIP 0402 220nF 6.3V X5R 10%", Case Code (Imperial)=0402, Case Code (Metric)=1005, Dielectric=X5R, Manufacturer=KEMET, Max Operating Temperature=85°C, Min Operating Temperature=-55°C, Tolerance=10%, Voltage=6.3V
D1 D2: library part D0026-A.4, "DIODE SCHOTTKY SMD 2A 60V SOD123FL", Forward Current=2A, Forward Voltage=0.6V, Manucturer Part Number 2=SS26L, Manufacturer=Nexperia
D3: library part D0029-A.2, "DIODE FAST SMD 200mA 100V SOD123", Manufacturer=Vishay
DL1: library part L0009-A.4, "LED SMD 0603 GREEN/568 15mcd 120^", Manufacturer=Broadcom
DL2 DL3: library part L0001-A.3, "LED SMD 0805 YELLOW CLEAR", Manufacturer=Kingbright, Manufacturer 2=Lite-On, Manufacturer Part Number 2=LTST-C170YKT
DL4 DL5 DL6 DL7 DL8: library part L0003-A.8, "LED RGB 2020", Manufacturer="Shenzhen LED Color Opto Electronic CO.,LTD."
FD1 FD2 FD3 FD4 FD5 FD6: library part UT0000-A.3
J1: library part J0011-A.1, "CONN Micro SD", Manufacturer=Amphenol
J2 J3 J4: library part J0274-A.1, "CONN GROVE SMD-90D(4+2P-2.0) 320110032", Manufacturer=Seeed, Manufacturer 2=4UCON, Manufacturer Part Number 2=215TW-511
J6: library part J0028-A.3, "CONN FPC/FFC 41POS .3MM", Current Rating=200mA, Flammability Rating="UL94 HB", Manufacturer=Hirose, Max Operating Temperature=85°C, Min Operating Temperature=-55°C, Voltage Rating=30V
J7 J8: library part J0053-A.6, "CONN BATTERY HOLDER 18650 CLIP SMT", Manufacturer="Keystone Electronics"
J9 J10: library part J0100-A.4, "TERM BLK 3P TOP ENTRY 2.5MM SMD", Color=Black, Current=5A, Current Rating=6A, Flammability Rating="UL94 V-0", Manufacturer="Phoenix Contact", Package Quantity=400, Voltage=150V, Voltage Rating=160V
J11: library part J0103-A.2, "CONN HEADER SMD 2 POS 0.079\" (2.00mm)", Manufacturer=JST, Part Number=B2B-PH-SM4-TBLFSN
J12: library part J0102-A.1, "CONN FPC SMD SKT 24 POS 0.5mm RA SMD", Contact Resistance=30mR, Current Rating=500mA, Flammability Rating="UL94 V-0", Housing Color=Black, Insulation Resistance=100MR, Manufacturer="Amphenol FCI", Max Operating Temperature=105°C, Max Voltage Rating (AC)=50V, Min Operating Temperature=-55°C, Package Quantity=3000
JANALOG1: library part J0098-A.5, "CONN STRIP SMD MKR F AREF", Manufacturer=4UCON
JDIGITAL1: library part J0099-A.6, "CONN STRIP SMD MKR F 5V", Manufacturer=4UCON
L6: library part I0013-A.5, "FIXED IND 10UH 1.3A 120 MOHM SMD", DC Resistance (DCR)=120mR, Frequency=30MHz, Manufacturer=Bourns, Max DC Current=1.3A, Max Operating Temperature=125°C, Min Operating Temperature=-40°C, Package Quantity=1000, Test Frequency=2.52MHz, Tolerance=20%
M1: library part S0011-A.4, "BUZZER 2 V, 4 V, 100 mA, 85 dB", Manufacturer="Multicomp Pro", Manufacturer 2=DB, Manufacturer Part Number 2=CDT092A3BILFMP-002
MKR1: library part UT0017-A.3, "MKR board SMD pads alternate"
PB1: library part B0013-A.8, "PUSHBUTTON SMD VERTICAL ANCHORS 4x3.4mm", Manufacturer=E-Switch, Max Operating Temperature=85°C, Min Operating Temperature=-35°C
Q1: library part T0004-A.3, "MOSFET N-CH 60V 300mA SOT23", Manufacturer="On Semiconductor", Manufacturer 2=Hottech, Manufacturer Part Number 2=2N7002K
Q2: library part T0012-A.6, "MOSFET N-CH 2x 60V 0.32A SOT363", Manufacturer=Nexperia
R1 R2 R4 R5 R10 R11 R12 R16 R19 R23 R38: library part R0003-A.11, "RES CHIP 0402 10K 1% 1/16W", Case Code (Imperial)=0402, Case Code (Metric)=1005, Manufacturer=Vishay, Manufacturer 2=Panasonic, Manufacturer Part Number 2=ERJ-2RKF1002X, Power=63mW, Tolerance=1%
R3: library part R0017-A.11, "RES CHIP 0402 330R 5% 1/16W", Case Code (Imperial)=0402, Case Code (Metric)=1005, Manufacturer=Vishay, Manufacturer 2=Panasonic, Manufacturer Part Number 2=ERJ-2GEJ331X, Power=63mW, Tolerance=5%
R6 R7: library part R0016-A.11, "RES CHIP 0402 270R 5% 1/16W", Case Code (Imperial)=0402, Case Code (Metric)=1005, Manufacturer=Yageo, Power=63mW, Tolerance=5%
R8 R9 R13 R14 R15 R17 R18 R20 R22 R24 R25 R26 R27 R33 R34 R35 R36 R37 R39 R40: library part R0000-A.11, "RES CHIP 0402 0R 1/16W", Case Code (Imperial)=0402, Case Code (Metric)=1005, Manufacturer=Vishay, Manufacturer 2=Panasonic, Manufacturer Part Number 2=ERJ-S020R00X, Power=63mW, Tolerance=J
R21 R41: library part R0170-A.10, "RES CHIP 0402 10R 1/16W 1%", Case Code (Imperial)=0402, Case Code (Metric)=1005, Manufacturer=Yageo, Max Operating Temperature=155°C, Min Operating Temperature=-55°C, Power=63mW, Resistance=10R, Temperature Coefficient=100ppm/°C, Tolerance=1%, Voltage Rating=50V
R28: library part R0009-A.11, "RES CHIP 0402 22R 1% 1/16W", Case Code (Imperial)=0402, Case Code (Metric)=1005, Manufacturer=Yageo, Power=63mW, Tolerance=1%
R29 R30: library part R0013-A.11, "RES CHIP 0402 4K7 1% 1/16W", Case Code (Imperial)=0402, Case Code (Metric)=1005, Manufacturer=Yageo, Power=63mW, Tolerance=1%
R31 R32: library part R0007-A.11, "RES CHIP 0402 1K 1% 1/16W", Case Code (Imperial)=0402, Case Code (Metric)=1005, Manufacturer=Vishay, Manufacturer 2=Panasonic, Manufacturer Part Number 2=ERJ-2RKF1001X, Power=63mW, Tolerance=1%
S1 S2: library part S0009-A.5, "RELAY GEN PURP 2A 220VDC 900MHz, DC Input SMT", Coil Current=28mA, Coil Power=140mW, Coil Resistance=178R, Coil Voltage (DC)=5V, Contact Current Rating=2A, Manufacturer="TE Connectivity", Manufacturer 2=KEMET, Manufacturer Part Number 2=EE2-5NU-L, Max Operating Temperature=85°C, Max Voltage Rating (AC)=250V, Max Voltage Rating (DC)=220V, Min Operating Temperature=-40°C, Package Quantity=500, Part Number=V23079-G2001-B301
U1: library part U0179-A.6, "IMU ACCEL/GYRO I2C/SPI 14VFLGA", Case/Package=LGA-14L, Manufacturer=STMicroelectronics, Max Operating Temperature=+85, Max Supply Voltage=3.6V, Min Operating Temperature=-40, Min Supply Voltage=1.7V
U2: library part U0136-A.7, "IC SENS OPT 560NM AMBIENT MODULE APDS-9960", Manufacturer=Broadcom
U3: library part U0125-A.8, "IC LED BOOST DRIVER PWM DIMMING VIN 2V7 TO 5V5 VOUT MAX 40V", Frequency=600kHz, Manufacturer="ON Semiconductor", Max Input Voltage=5.5V, Max Operating Temperature=85°C, Max Output Voltage=39V, Min Input Voltage=2.7V, Min Operating Temperature=-30°C, Min Output Voltage=37V, Nominal Input Voltage (DC)=3.6V, Output Current per Channel=700mA, Package Quantity=3000
U4: library part U0183-A.3, "SENSOR PRESSURE TEMPERATURE HUMIDITY", Manufacturer="Bosch Sensortec", Max Operating Temperature=85°C, Min Operating Temperature=-40°C
U5: library part U0249-A.2, "IC EXTENDED I/O EXPANDER I2C 8-bit", Manufacturer=NXP, Max Operating Temperature=85°C, Max Supply Voltage=6V, Min Operating Temperature=-40°C, Min Supply Voltage=2.5V
U6: library part U0264-A.4, "IC WHITE LED DRIVER W/PW DIM 26V TDFN-EP-8", Manufacturer=Renesas, Max Operating Temperature=85°C, Max Supply Voltage=5.5V, Min Operating Temperature=-40°C, Min Supply Voltage=2.4V

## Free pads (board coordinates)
  round 0 hole 2.5 unplated: H1(-39.75,0) H2(19.875,34.425) H3(19.875,-34.425)
  round 2.35 smd far side: H8(35.5,-17.049) H9(19.5,-17.049) H10(-19.5,-17.049) H11(-35.5,-17.049)
  round 0 hole 0.5 unplated: MOUSEBITES(-31.923,-28.245) MOUSEBITES(-31.809,28.403) MOUSEBITES(-31.323,-28.945) MOUSEBITES(-31.209,29.103) MOUSEBITES(-30.662,-29.61) MOUSEBITES(-30.509,29.803) MOUSEBITES(-30.023,-30.245) MOUSEBITES(-29.909,30.403) MOUSEBITES(-29.423,-30.845) MOUSEBITES(-29.309,31.003) MOUSEBITES(29.296,30.991) MOUSEBITES(29.421,-30.7) MOUSEBITES(29.896,30.391) MOUSEBITES(30.021,-30.1) MOUSEBITES(30.496,29.791) MOUSEBITES(30.621,-29.5) MOUSEBITES(31.196,29.091) MOUSEBITES(31.321,-28.8) MOUSEBITES(31.796,28.391) MOUSEBITES(31.921,-28.1)

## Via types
v1: diameter 0.6, hole 0.3, Top to Bottom, tented both sides, 142 vias

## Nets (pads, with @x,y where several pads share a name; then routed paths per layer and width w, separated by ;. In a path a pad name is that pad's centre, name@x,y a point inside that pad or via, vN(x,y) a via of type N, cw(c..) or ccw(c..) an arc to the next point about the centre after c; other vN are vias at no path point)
+3V3: C1.2 C2.2 C4.2 C6.2 C14.1 C15.2 J1.4 J2.3 J3.3 J4.3 J6.7 J6.8 J6.9 J12.20 J12.21 JDIGITAL1.12 L6.1 M1.1 MKR1.VCC R1.2 R2.2 R10.2 R11.2 R12.2 R16.2 R20.2 R23.2 R28.2 R30.1 R31.2 U1.5 U1.8 U1.12 U2.5 U3.6 U4.2 U4.6 U4.8 U6.2 | length 207.3
  Top w0.2: R30.1@-21.883,16.437 -21.883,14.285 -21.451,13.852 -19.498,13.852 M1.1@-19.404,13.946 ; v1(-4.8,3.051) R2.2@-4,3.051 R1.2@-2.8,3.051 ; C6.2@3.107,7.526 v1(4.336,7.526) ; L6.1@4.175,12.121 4.336,11.959 4.336,9.128 ; U3.6@4.5,6.693 4.5,7.362 v1(4.336,7.526) ; U6.2@8.468,7.261 8.481,7.275 8.481,8.25 7.602,9.128 4.336,9.128 ; v1(4.336,7.526) 4.336,9.128
  Top w0.3: M1.1@-19.286,13.629 -19.286,14.198 -18.554,14.93 v1(-16.929,14.93) ; v1(-12.98,3.736) v1@-12.975,3.741 ; v1(-0.346,-36.097) -0.102,-36.34 J1.4@-0.102,-37.694 ; v1(10.86,8.086) 10.86,10.012 11.232,10.383 13.141,10.383 13.491,10.734 13.491,11.465 13.667,11.64 13.857,11.64 14.244,12.028 R20.2@14.259,12.028 ; 11.459,23.183 11.459,22.244 11.752,21.951 R31.2@12.5,21.951
  Top w0.5: J3.3@-18.67,25.487 -18.67,25.694 -19.748,26.772 -19.748,27.679 -18.624,28.803 -13.901,28.803 -6.922,21.824 -6.922,21.722 -6.557,21.357 v1(-6.557,20.388) ; -6.557,21.443 -6.051,21.949 -6.051,30.651 J2.3@-6.246,30.846 ; J2.3@-6.336,30.902 -6.783,32.84 -6.151,33.636 4.608,33.636 5.02,33.223 7.525,33.223 7.938,32.811 7.938,32.78 8.462,32.256 8.28,31.467 J4.3@8.003,30.382 7.86,30.239 7.86,28.078 11.459,24.479 11.459,23.183 ; JDIGITAL1.12@10.176,-0.569 10.188,-0.581 10.188,-2.688 v1(10.2,-2.7)
  PWR w0.5: v1(-12.98,3.736) -12.98,3.179 -11.454,1.653 -5.337,1.653 -4.8,2.189 v1(-4.8,3.051)
  MID w0.3: v1(-16.929,14.93) -14.555,12.555 -14.555,12.314
  MID w0.5: v1(-11.421,-39.566) -10.059,-38.204 ; v1(-11.215,-37.385) -10.395,-38.204 -10.059,-38.204 ; v1@-0.365,-36.116 -0.392,-36.116 -0.553,-36.277 -4.399,-36.277 -6.326,-38.204 v1(-8.548,-38.204) -10.059,-38.204 ; 5.855,-30.969 5.963,-30.861 v1(7.463,-30.861) 10.064,-30.861 12.318,-28.607 v1(12.318,-26.264)
  Bottom w0.2: C1.2@-13.886,-38.989 -13.878,-38.98 -13.176,-38.98 -13.109,-38.913 U4.8@-12.03,-38.913 -12.03,-39.448 -11.913,-39.566 v1(-11.421,-39.566) ; R16.2@-12.833,-37.355 -12.072,-37.355 U4.6@-12.03,-37.313 -11.995,-37.349 -11.251,-37.349 v1(-11.215,-37.385) ; U4.2@-9.63,-38.113 -8.857,-38.113 -8.756,-38.214 -8.558,-38.214 v1(-8.548,-38.204) -8.539,-38.195 -7.547,-38.195 C2.2@-7.538,-38.186 ; J6.7@-4.8,4.325 v1(-4.8,3.051) ; J6.8@-4.5,1.45 -4.5,2.71 -4.8,3.01 v1(-4.8,3.051) ; J6.9@-4.2,4.325 -4.2,3.651 v1(-4.8,3.051) ; U1.8@-1.175,-2.45 U1.8@-1.375,-2.45 -2.433,-2.45 -3.002,-1.881 -3.002,-0.457 v1(-2.323,0.222) -1.89,-0.21 -0.74,-0.21 U1.12@-0.5,-0.45 ; U1.5@0.5,-2.8 0.5,-3.3 0.7,-3.5 C4.2@2.4,-3.5 ; R28.2@6.319,-30.059 6.324,-30.063 6.324,-30.657 6.528,-30.861 v1(7.463,-30.861) ; C14.1@12.246,-27.117 12.279,-27.085 12.279,-26.303 v1(12.318,-26.264) ; U2.5@12.248,-28.813 C14.1@12.248,-27.119
  Bottom w0.3: v1(-16.929,14.93) -15.947,14.93 -13.908,12.891 -12.473,12.891 -10.872,14.492 -10.872,14.825 -6.557,19.14 v1(-6.557,20.388) ; J12.21@-7.06,-5 -7.06,-6.479 -6.9,-6.639 v1(-6.9,-6.749) -6.56,-6.409 J12.20@-6.56,-5 -6.56,-3.889 -7,-3.449 R23.2@-7,-3.149 ; C4.2@2.4,-3.5 2.4,-2.345 3,-1.745 v1(3,-0.253) ; v1(4.336,7.526) 4.336,7.513 4.776,7.074 4.776,6.899 5.423,6.251 10.019,6.251 10.877,7.109 v1@10.877,8.008 ; v1(10.2,-2.7) 10.2,-0.7 11.275,0.375 R11.2@11.275,0.973 13.173,0.973 13.678,1.478 13.678,2.749 ; v1(10.86,8.086) 10.877,8.069 v1@10.877,8.008 ; R10.2@11.275,2.749 13.678,2.749 ; v1@10.877,8.008 11.275,7.61 R12.2@11.275,5.547 12.853,5.547 13.678,4.722 13.678,2.749
+5V: C3.2 C8.2 C10.2 C11.2 C12.2 C13.2 D1.C D2.C DL1.A DL4.3 DL5.3 DL6.3 DL7.3 DL8.3 JDIGITAL1.14 MKR1.5V R22.1 R38.2 R39.2 S1.1 S1.9 S2.1 S2.9 U5.16 | length 205.9
  Top w0.25: DL1.A@27,28.743 27,29.682 26.123,30.559 15.669,30.559 14.767,29.657 14.767,25.088 19.047,20.808 27.089,20.808 27.904,19.993
  Top w0.3: v1(-10.244,14.565) -9.781,15.028 -9.521,15.028 R39.2@-9.473,15.077 ; v1(-1.08,18.149) -1.08,18.068 -1.427,17.721 -1.427,13.851 -1.149,13.573 U5.16@0.475,13.573 2.005,13.573 2.181,13.397 2.181,13.003 2.639,12.545 R38.2@2.639,10.81 ; R22.1@15.241,12.041 15.341,12.14 16.465,12.14 16.841,11.764 16.841,11.003 16.832,10.995 16.832,9.956 v1(16.824,9.947)
  Top w0.5: v1(18.1,3.5) 18.127,3.5 18.397,3.23 27.594,3.23 27.904,3.54 S1.9@27.904,5.29
  Top w0.54: v1(12.9,-0.326) 13.143,-0.569 JDIGITAL1.14@15.256,-0.569 ; D1.C@15.68,1.931 15.68,1.376 15.403,1.099 15.403,-0.421 JDIGITAL1.14@15.256,-0.569 ; D2.C@16.841,11.003 20.272,11.003 S2.1@20.284,11.015 ; S1.1@20.284,-2.01 20.284,-1.476 20.054,-1.246 15.256,-1.246 JDIGITAL1.14@15.256,-0.569
  Top w1: v1(9.6,-7.749) 10.8,-7.749 11.1,-8.049 30.758,-8.049 ccw(c30.758,-6.358) 31.954,-7.554 32.798,-6.71 ccw(c31.002,-4.914) 33.542,-4.914 33.542,17.162 33.542,17.165 ccw(c30.102,17.169) 32.529,19.608 31.852,20.284 ccw(c31.144,19.579) 31.144,20.579 28.904,20.579 ccw(c28.904,19.579) 28.197,20.286 27.904,19.993 S2.9@27.904,18.315
  MID w0.5: v1(-16.101,7.786) -14.214,7.786 -13.475,8.525 -13.475,11.334 v1(-10.244,14.565) v1@-10.211,14.598 ; v1@-10.187,14.623 -6.277,14.623 -2.751,18.149 v1(-1.08,18.149)
  Bottom w0.3: DL7.3@-19.046,11.214 -18.788,11.214 -18.594,11.02 -17.96,11.02 -17.792,10.851 C12.2@-17.636,10.851 -17.741,10.722 -18.1,10.1 ; DL8.3@-18.796,-11.977 -17.776,-10.957 C13.2@-17.703,-10.957 ; v1(-1.08,18.149) -0.438,18.791 C11.2@-0.438,20.694 -0.438,20.993 -0.845,21.4 -0.845,22.095 DL6.3@-0.85,22.1 ; v1(11.369,-5.906) 13.657,-5.906 17.4,-9.649 18.031,-10.013 C8.2@18.198,-10.003 18.21,-9.99 19.131,-9.99 DL4.3@19.534,-10.393 ; v1(16.824,9.947) 17.147,9.624 17.22,9.624 ; v1(18.1,3.5) 16.469,5.131 16.469,8.933 17.05,9.514 17.11,9.514 17.22,9.624 ; DL5.3@18.824,11.301 18.75,11.301 18.3,10.851 18.3,10.704 C10.2@17.817,10.221 17.22,9.624
  Bottom w0.5: -18.1,10.1 -18.1,9.4 -17.7,9 -17.314,9 v1(-16.101,7.786) -16.101,7.759 -15.8,7.458 -15.8,-9.216 -17.176,-10.592 C13.2@-17.718,-10.925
